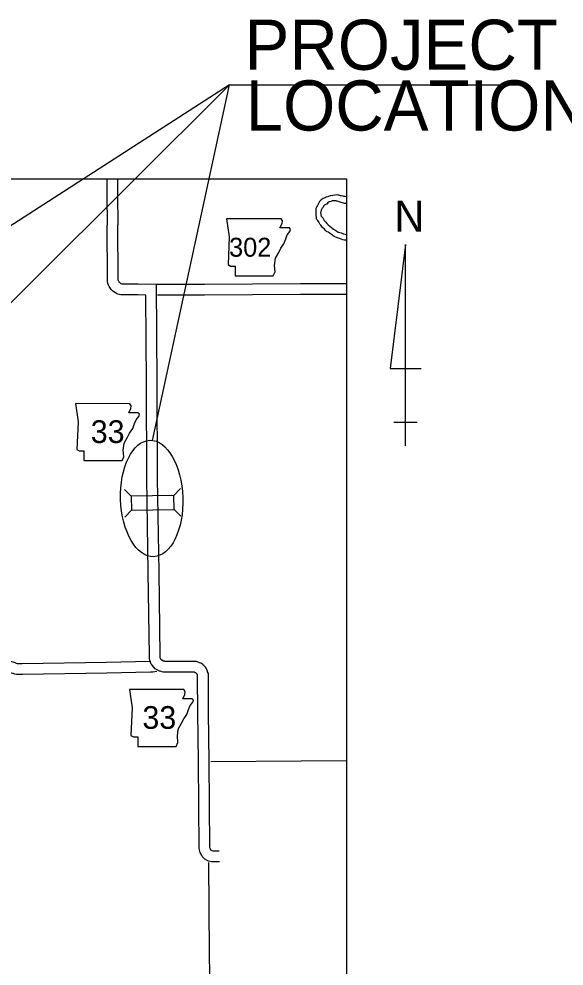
# Model space of a CAD drawing. Extents: x 982240 to 1103002, y 974866 to 1054902.
# Drawn here: x 999731 to 1011132, y 1035077 to 1054902 of the extents above; entities that cross this region are included whole.
import ezdxf

# ---------------------------------------------------------------- set-up
doc = ezdxf.new("R2010")
doc.units = 0
for name, color, linetype in [('Level 10', 7, 'Continuous'), ('Level 2', 7, 'Continuous'), ('Level 20', 7, 'Continuous'), ('Level 21', 7, 'Continuous'), ('Level 9', 7, 'Continuous'), ('R_Draft', 7, 'Continuous')]:
    doc.layers.add(name, color=color, linetype=linetype)

msp = doc.modelspace()

# ---------------------------------------------------------------- linework, layer by layer
at = {"layer": 'Level 10'}
for points in [[(1001566, 1051554), (1001568, 1051220), (1001574, 1050588)], [(1001791, 1051554), (1001793, 1051222), (1001799, 1050591)], [(1002383, 1049123), (1002222, 1049124), (1001910, 1049124), (1001888, 1049124), (1001860, 1049125), (1001824, 1049134), (1001802, 1049143), (1001770, 1049156), (1001750, 1049168), (1001718, 1049189), (1001689, 1049214), (1001660, 1049241), (1001636, 1049273), (1001620, 1049301), (1001603, 1049333), (1001592, 1049368), (1001585, 1049404), (1001582, 1049447), (1001574, 1050589)], [(1002606, 1049347), (1002223, 1049349), (1001907, 1049349), (1001892, 1049349), (1001888, 1049351), (1001872, 1049357), (1001870, 1049358), (1001853, 1049369), (1001840, 1049381), (1001827, 1049393), (1001824, 1049397), (1001817, 1049409), (1001811, 1049420), (1001811, 1049422), (1001809, 1049433), (1001807, 1049456), (1001799, 1050590)], [(1002606, 1049350), (1003613, 1049352), (1005619, 1049364), (1006582, 1049364)], [(1002733, 1041466), (1002694, 1041509), (1002692, 1041517), (1002686, 1041531), (1002685, 1041534), (1002684, 1041537), (1002683, 1041551), (1002683, 1041555), (1002683, 1041576), (1002662, 1043327), (1002632, 1045285), (1002624, 1047276), (1002606, 1049350)], [(1002630, 1049125), (1003614, 1049127), (1005620, 1049139), (1006582, 1049139)], [(1002580, 1041300), (1002514, 1041373), (1002497, 1041399), (1002487, 1041420), (1002481, 1041437), (1002473, 1041456), (1002466, 1041482), (1002461, 1041507), (1002458, 1041538), (1002458, 1041554), (1002458, 1041576), (1002437, 1043324), (1002407, 1045283), (1002399, 1047275), (1002383, 1049123)], [(1002465, 1041454), (1001565, 1041434), (999797, 1041407), (999745, 1041404), (999707, 1041405), (999699, 1041407), (999680, 1041412), (999650, 1041424), (999608, 1041436), (999579, 1041446), (999532, 1041456), (999511, 1041462), (999477, 1041473), (999438, 1041481), (999413, 1041485), (999381, 1041492), (999347, 1041498), (999309, 1041503), (999193, 1041501), (997535, 1041478)], [(1003696, 1040391), (1003693, 1041127), (1003693, 1041155), (1003692, 1041202), (1003678, 1041235), (1003675, 1041248), (1003663, 1041284), (1003646, 1041310), (1003632, 1041331), (1003613, 1041353), (1003596, 1041371), (1003580, 1041383), (1003567, 1041395), (1003532, 1041418), (1003509, 1041426), (1003492, 1041434), (1003443, 1041449), (1003344, 1041454), (1002804, 1041454), (1002786, 1041454), (1002785, 1041454), (1002779, 1041456), (1002769, 1041459), (1002757, 1041462), (1002735, 1041472), (1002722, 1041480), (1002701, 1041491)], [(1002612, 1041246), (1002575, 1041236), (1002534, 1041231), (1002482, 1041229), (1001569, 1041209), (999805, 1041182), (999749, 1041179), (999681, 1041180), (999646, 1041188), (999609, 1041198), (999577, 1041210), (999539, 1041222), (999519, 1041229), (999477, 1041238), (999446, 1041247), (999421, 1041254), (999395, 1041260), (999369, 1041265), (999339, 1041271), (999315, 1041275), (999295, 1041277), (999196, 1041276), (997538, 1041253)], [(1003471, 1040390), (1003468, 1041124), (1003468, 1041149), (1003468, 1041153), (1003463, 1041165), (1003458, 1041186), (1003451, 1041196), (1003446, 1041202), (1003435, 1041210), (1003430, 1041215), (1003412, 1041223), (1003403, 1041226), (1003338, 1041229), (1002800, 1041229), (1002768, 1041230), (1002748, 1041232), (1002722, 1041238), (1002705, 1041243), (1002686, 1041249), (1002674, 1041252), (1002643, 1041265), (1002635, 1041270), (1002619, 1041277), (1002609, 1041285), (1002580, 1041300)], [(1003484, 1039352), (1003471, 1040389)], [(1003709, 1039355), (1003696, 1040392)], [(1003925, 1037259), (1003799, 1037257), (1003757, 1037262), (1003694, 1037275), (1003621, 1037313), (1003564, 1037371), (1003539, 1037418), (1003519, 1037456), (1003498, 1037535), (1003484, 1039352)], [(1003922, 1037484), (1003812, 1037482), (1003793, 1037485), (1003769, 1037489), (1003756, 1037496), (1003747, 1037505), (1003738, 1037523), (1003730, 1037537), (1003723, 1037565), (1003709, 1039354)]]:
    msp.add_lwpolyline(points, dxfattribs=at)
at = {"layer": 'Level 2'}
for points in [[(1003741, 1039358), (1005636, 1039375), (1006582, 1039383)], [(1003716, 1035338), (1003704, 1037246)], [(1003745, 1033554), (1003716, 1035338)]]:
    msp.add_lwpolyline(points, dxfattribs=at)
at = {"layer": 'Level 20'}
for p, q in [((1002080, 1044916), (1001937, 1045054)), ((1002970, 1044930), (1003108, 1045072)), ((1002084, 1044620), (1001946, 1044477)), ((1002975, 1044633), (1003117, 1044495))]:
    msp.add_line(p, q, dxfattribs=at)
msp.add_lwpolyline([(1002084, 1044620), (1002975, 1044633), (1002970, 1044930), (1002080, 1044916)], close=True, dxfattribs=at)
at = {"layer": 'Level 21'}
for points in [[(1004074, 1050718), (1004131, 1050338), (1004105, 1049760), (1004156, 1049729), (1004251, 1049729), (1004251, 1049526), (1005051, 1049526), (1005089, 1049608), (1005076, 1049741), (1005095, 1049894), (1005165, 1050014), (1005209, 1050103), (1005273, 1050198), (1005311, 1050300), (1005343, 1050382), (1005400, 1050452), (1005412, 1050496), (1005387, 1050528), (1005190, 1050528), (1005235, 1050617), (1005241, 1050674), (1005215, 1050718)], [(1000911, 1046850), (1000968, 1046469), (1000943, 1045892), (1000993, 1045860), (1001088, 1045860), (1001088, 1045657), (1001888, 1045657), (1001926, 1045739), (1001913, 1045873), (1001932, 1046025), (1002002, 1046145), (1002046, 1046234), (1002110, 1046329), (1002148, 1046431), (1002180, 1046513), (1002237, 1046583), (1002249, 1046628), (1002224, 1046659), (1002027, 1046659), (1002072, 1046748), (1002078, 1046805), (1002052, 1046849)], [(1002042, 1040864), (1002099, 1040483), (1002074, 1039906), (1002125, 1039874), (1002220, 1039874), (1002220, 1039671), (1003019, 1039671), (1003057, 1039754), (1003045, 1039887), (1003064, 1040039), (1003133, 1040160), (1003178, 1040249), (1003241, 1040344), (1003279, 1040445), (1003311, 1040528), (1003368, 1040598), (1003381, 1040642), (1003356, 1040674), (1003159, 1040674), (1003203, 1040763), (1003210, 1040820), (1003183, 1040864)]]:
    msp.add_lwpolyline(points, close=True, dxfattribs=at)
at = {"layer": 'Level 9'}
for points in [[(1006582, 1051176), (1006553, 1051185), (1006526, 1051189), (1006512, 1051191), (1006473, 1051198), (1006458, 1051201), (1006440, 1051208), (1006421, 1051215), (1006400, 1051217), (1006376, 1051220), (1006337, 1051213), (1006295, 1051207), (1006241, 1051201), (1006202, 1051187), (1006154, 1051170), (1006116, 1051152), (1006097, 1051142), (1006074, 1051133), (1006052, 1051119), (1006036, 1051104), (1006018, 1051082), (1006007, 1051063), (1006001, 1051050), (1005990, 1051027), (1005976, 1051000), (1005961, 1050974), (1005950, 1050950), (1005942, 1050931), (1005938, 1050912), (1005937, 1050886), (1005938, 1050862), (1005942, 1050836), (1005944, 1050822), (1005943, 1050806), (1005943, 1050794), (1005941, 1050784), (1005944, 1050766), (1005948, 1050754), (1005951, 1050748), (1005950, 1050731)], [(1006088, 1050736), (1006077, 1050747), (1006060, 1050768), (1006056, 1050780), (1006054, 1050796), (1006052, 1050806), (1006050, 1050812), (1006049, 1050825), (1006047, 1050836), (1006046, 1050848), (1006047, 1050859), (1006049, 1050869), (1006052, 1050881), (1006058, 1050894), (1006062, 1050905), (1006069, 1050920), (1006075, 1050934), (1006083, 1050947), (1006089, 1050956), (1006094, 1050963), (1006101, 1050973), (1006105, 1050979), (1006111, 1050988), (1006113, 1050994), (1006119, 1051000), (1006123, 1051005), (1006130, 1051010), (1006136, 1051015), (1006143, 1051021), (1006151, 1051025), (1006164, 1051030), (1006173, 1051031), (1006179, 1051033), (1006187, 1051035), (1006194, 1051038), (1006194, 1051041), (1006195, 1051046), (1006195, 1051049), (1006194, 1051054), (1006191, 1051057), (1006190, 1051058), (1006190, 1051059), (1006190, 1051061), (1006191, 1051062), (1006199, 1051068), (1006202, 1051070), (1006207, 1051075), (1006225, 1051079), (1006233, 1051081), (1006243, 1051084), (1006260, 1051091), (1006276, 1051097), (1006287, 1051099), (1006299, 1051100), (1006313, 1051102), (1006333, 1051104), (1006350, 1051102), (1006367, 1051098), (1006386, 1051093), (1006419, 1051083), (1006466, 1051067), (1006488, 1051061), (1006515, 1051056), (1006542, 1051048), (1006572, 1051043), (1006582, 1051040)], [(1006582, 1050268), (1006569, 1050270), (1006533, 1050271), (1006504, 1050277), (1006468, 1050292), (1006433, 1050307), (1006396, 1050318), (1006370, 1050328), (1006340, 1050344), (1006324, 1050351), (1006304, 1050363), (1006288, 1050374), (1006268, 1050388), (1006248, 1050402), (1006216, 1050424), (1006203, 1050437), (1006178, 1050447), (1006162, 1050456), (1006149, 1050470), (1006138, 1050483), (1006122, 1050501), (1006084, 1050531), (1006075, 1050545), (1006060, 1050563), (1006043, 1050584), (1006026, 1050608), (1006012, 1050634), (1006001, 1050653), (1005976, 1050688), (1005964, 1050705), (1005956, 1050720), (1005950, 1050731)], [(1006088, 1050736), (1006117, 1050684), (1006142, 1050658), (1006172, 1050620), (1006200, 1050595), (1006231, 1050567), (1006266, 1050537), (1006280, 1050524), (1006308, 1050504), (1006335, 1050485), (1006379, 1050458), (1006408, 1050442), (1006439, 1050433), (1006470, 1050424), (1006517, 1050407), (1006557, 1050395), (1006582, 1050388)]]:
    msp.add_lwpolyline(points, dxfattribs=at)
at = {"layer": 'R_Draft'}
for p, q in [((1002525, 1046079), (1004138, 1053520)), ((1004138, 1053520), (1010390, 1053520)), ((1007818, 1050180), (1007494, 1047588)), ((1007818, 1045968), (1007818, 1050180)), ((1007494, 1047588), (1008142, 1047588)), ((1007574, 1046460), (1008060, 1046460))]:
    msp.add_line(p, q, dxfattribs=at)
msp.add_lwpolyline([(991692, 1041115), (1004138, 1053520), (991631, 1045465)], dxfattribs=at)
msp.add_lwpolyline([(984683, 1051554), (1006582, 1051554), (1006582, 1032484), (984683, 1032484)], close=True, dxfattribs=at)
msp.add_ellipse((1002508, 1044864), major_axis=(41, -1218), ratio=0.533954, dxfattribs=at)

# ---------------------------------------------------------------- texts
at = {"layer": 'Level 21'}
for s, height, p in [('302', 396, (1004126, 1049926)), ('33', 475.2, (1001233, 1046026)), ('33', 475.2, (1002313, 1040043))]:
    msp.add_text(s, height=height, dxfattribs=at).set_placement(p)
at = {"layer": 'R_Draft'}
for s, height, p in [('PROJECT', 1050, (1004450, 1053837)), ('LOCATION', 1050, (1004474, 1052566)), ('N', 648, (1007584, 1050450))]:
    msp.add_text(s, height=height, dxfattribs=at).set_placement(p)

doc.saveas('drawing.dxf')
